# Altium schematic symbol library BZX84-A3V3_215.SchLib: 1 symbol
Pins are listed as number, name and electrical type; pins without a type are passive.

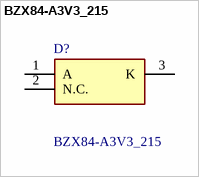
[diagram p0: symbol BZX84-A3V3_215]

## BZX84-A3V3_215
designator D?
NEXPERIA - BZX84-A3V3,215 - ZENER DIODE, 0.25W, 3.3V, SOT-23, REEL; Geometry.Height: 1.1mm
footprint SOT95P230X110-3N
pins: 1 A, 2 N.C., 3 K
